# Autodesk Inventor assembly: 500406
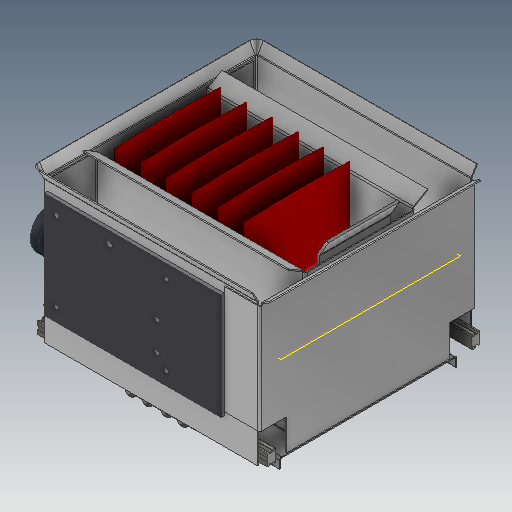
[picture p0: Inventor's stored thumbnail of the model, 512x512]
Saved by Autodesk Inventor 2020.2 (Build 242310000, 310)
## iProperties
RuleStatus: InUse
Shininess: 0.0
Length Units: 11269
Angle Units: 11279
Time Units: 11290
Mass Units: 11283
Length Display Precision: 3
Angle Display Precision: 2
Compacted: True
Created: 2000-01
Part Number: 500406
Document SubType Name: Assembly
Designer: glanglot
Mass: 8116.9 g
Surface Area: 15485.2 cm^2
Volume: 2060.68 cm^3
Density: 3.93894 g/cm^3
Density: 0.0
Volumn: 0.0
Area: 0.0
PropertySet Name: Model Information
Control State: 0
Checked Out: False
Master: False
Dimensions: 342,2x241,9x339,5 mm
Mass: 8,117 kg
DocNumber: 500406.iam
Folder: 01 - Themengebiete\Simplification\01 - Packaging machine\
VDS_Category: 3D Komponenten
Author: glanglot
Revision Number: -
Title: box
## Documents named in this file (14)
- D:\07 - DEMODATEN\OTX 2019 - Dataset - UPDATE - Dez2019\Designs\07-Packing machine\500406.iam
- D:\07 - DEMODATEN\OTX 2019 - Dataset - UPDATE - Dez2019\Designs\07-Packing machine\Parts\ADSK-011378.ipt
- D:\07 - DEMODATEN\OTX 2019 - Dataset - UPDATE - Dez2019\Designs\07-Packing machine\500383.iam
- D:\07 - DEMODATEN\OTX 2019 - Dataset - UPDATE - Dez2019\Designs\07-Packing machine\500409.iam
- D:\07 - DEMODATEN\OTX 2019 - Dataset - UPDATE - Dez2019\Designs\07-Packing machine\17oz pouch pack pattern.iam
- D:\07 - DEMODATEN\OTX 2019 - Dataset - UPDATE - Dez2019\Designs\07-Packing machine\A105193.iam
- D:\07 - DEMODATEN\OTX 2019 - Dataset - UPDATE - Dez2019\Designs\07-Packing machine\500430.iam
- D:\07 - DEMODATEN\OTX 2019 - Dataset - UPDATE - Dez2019\Designs\07-Packing machine\Parts\ADSK-011396.ipt
- D:\07 - DEMODATEN\OTX 2019 - Dataset - UPDATE - Dez2019\Designs\07-Packing machine\Parts\ADSK-011810.ipt
- D:\07 - DEMODATEN\OTX 2019 - Dataset - UPDATE - Dez2019\Designs\07-Packing machine\A105192.iam
- D:\07 - DEMODATEN\OTX 2019 - Dataset - UPDATE - Dez2019\Designs\07-Packing machine\500445.iam
- D:\07 - DEMODATEN\OTX 2019 - Dataset - UPDATE - Dez2019\Designs\07-Packing machine\500447.iam
- D:\07 - DEMODATEN\OTX 2019 - Dataset - UPDATE - Dez2019\Designs\07-Packing machine\500550.iam
- D:\07 - DEMODATEN\OTX 2019 - Dataset - UPDATE - Dez2019\Content Center Files\de-DE\ISO 4762(2)\ISO 4762 - M4 x 16ISO.ipt
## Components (26 placed, 13 different names)
1. 500383:1 [sub-assembly] — Mate:2, Flush:3, Mate:4, Flush:4, Mate:6, Mate:7, Mate:8, Flush:8, Mate:10, Flush:10, Flush:11, Flush:12, Passend:21, Passend:22, Passend:27, Passend:28, Passend:29, Fluchtend:17, Fluchtend:21
2. ADSK-011378:1 — Passend:24, Passend:25, Passend:26
3. 500409:1 [sub-assembly] — Insert:3, Insert:4, Passend:19, Passend:20, Passend:23, Passend:25, Passend:26
4. 17oz pouch pack pattern:1 [sub-assembly] — Passend:40, Fluchtend:20, Fluchtend:21
5. A105193:1 [sub-assembly] — Mate:2, Flush:3, Passend:19, Passend:20, Passend:22, Passend:23
6. A105193:2 [sub-assembly] — Mate:4, Flush:4, Passend:21
7. 500430:1 [sub-assembly] — Passend:27, Passend:28, Passend:29, Passend:30, Passend:31, Passend:32, Passend:33
8. ADSK-011396:1 — Insert:3, Insert:4, Passend:24
9. A105192:1 [sub-assembly] — Flush:13, Mate:13, Passend:38
10. ADSK-011810:1 — Mate:6, Flush:7, Flush:13, Mate:13, Flush:15, Mate:15, Fluchtend:17, Fluchtend:18
11. A105192:2 [sub-assembly] — Flush:14, Mate:14, Passend:36, Passend:37, STROKE_02
12. ADSK-011810:2 — Mate:7, Flush:7, Mate:8, Flush:14, Mate:14, Flush:16, Mate:17, Fluchtend:18, STROKE_01, STROKE_02
13. 500445:1 [sub-assembly] — Flush:8, Passend:36, Passend:37, Passend:38, Fluchtend:20
14. A105192:3 [sub-assembly] — Flush:15, Mate:15, Mate:16, Passend:34
15. A105192:4 [sub-assembly] — Flush:16, Mate:17, Mate:18, Passend:35, STROKE_01
16. 500447:1 [sub-assembly] — Mate:10, Mate:16, Mate:18, Passend:34, Passend:35
17. 500550:1 [sub-assembly] — Passend:31, Passend:32
18. 500550:2 [sub-assembly] — Passend:30, Passend:33
19. ISO 4762 M4 x 16:1
20. ISO 4762 M4 x 16:2
21. ISO 4762 M4 x 16:3
22. ISO 4762 M4 x 16:4
23. ISO 4762 M4 x 16:5
24. ISO 4762 M4 x 16:6
25. ISO 4762 M4 x 16:7
26. ISO 4762 M4 x 16:8
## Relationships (52: Mate 34, Flush 16, Insert 2)
- STROKE_01 [Flush]: ADSK-011810:2 ↔ A105192:4
- STROKE_02 [Mate]: A105192:2 ↔ ADSK-011810:2
- Mate:2: 500383:1 ↔ A105193:1
- Flush:3: 500383:1 ↔ A105193:1
- Mate:4: 500383:1 ↔ A105193:2
- Flush:4: 500383:1 ↔ A105193:2
- Insert:3: 500409:1 ↔ ADSK-011396:1
- Insert:4: 500409:1 ↔ ADSK-011396:1
- Mate:6: 500383:1 ↔ ADSK-011810:1
- Mate:7: 500383:1 ↔ ADSK-011810:2
- Flush:7: ADSK-011810:1 ↔ ADSK-011810:2
- Mate:8: 500383:1 ↔ ADSK-011810:2
- Flush:8: 500383:1 ↔ 500445:1
- Mate:10: 500383:1 ↔ 500447:1
- Flush:10: 500383:1
- Flush:11: 500383:1
- Flush:12: 500383:1
- Flush:13: A105192:1 ↔ ADSK-011810:1
- Mate:13: A105192:1 ↔ ADSK-011810:1
- Flush:14: A105192:2 ↔ ADSK-011810:2
- Mate:14: A105192:2 ↔ ADSK-011810:2
- Flush:15: ADSK-011810:1 ↔ A105192:3
- Mate:15: ADSK-011810:1 ↔ A105192:3
- Mate:16: A105192:3 ↔ 500447:1
- Flush:16: ADSK-011810:2 ↔ A105192:4
- Mate:17: ADSK-011810:2 ↔ A105192:4
- Mate:18: A105192:4 ↔ 500447:1
- Passend:19 [Mate]: 500409:1 ↔ A105193:1
- Passend:20 [Mate]: 500409:1 ↔ A105193:1
- Passend:21 [Mate]: 500383:1 ↔ A105193:2
- Passend:22 [Mate]: 500383:1 ↔ A105193:1
- Passend:23 [Mate]: 500409:1 ↔ A105193:1
- Passend:24 [Mate]: ADSK-011378:1 ↔ ADSK-011396:1
- Passend:25 [Mate]: ADSK-011378:1 ↔ 500409:1
- Passend:26 [Mate]: ADSK-011378:1 ↔ 500409:1
- Passend:27 [Mate]: 500383:1 ↔ 500430:1
- Passend:28 [Mate]: 500383:1 ↔ 500430:1
- Passend:29 [Mate]: 500383:1 ↔ 500430:1
- Passend:30 [Mate]: 500430:1 ↔ 500550:2
- Passend:31 [Mate]: 500430:1 ↔ 500550:1
- Passend:32 [Mate]: 500430:1 ↔ 500550:1
- Passend:33 [Mate]: 500430:1 ↔ 500550:2
- Passend:34 [Mate]: A105192:3 ↔ 500447:1
- Passend:35 [Mate]: A105192:4 ↔ 500447:1
- Passend:36 [Mate]: A105192:2 ↔ 500445:1
- Passend:37 [Mate]: A105192:2 ↔ 500445:1
- Fluchtend:17 [Flush]: 500383:1 ↔ ADSK-011810:1
- Fluchtend:18 [Flush]: ADSK-011810:1 ↔ ADSK-011810:2
- Passend:38 [Mate]: A105192:1 ↔ 500445:1
- Passend:40 [Mate]: 17oz pouch pack pattern:1
- Fluchtend:20 [Flush]: 17oz pouch pack pattern:1 ↔ 500445:1
- Fluchtend:21 [Flush]: 500383:1 ↔ 17oz pouch pack pattern:1
## Named parameters: STROKE = 0.5 mm
